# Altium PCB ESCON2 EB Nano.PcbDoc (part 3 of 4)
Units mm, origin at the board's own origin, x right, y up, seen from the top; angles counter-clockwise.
Board outline 67 x 70 mm, 6 copper layers (Top Side, Mid Layer 1, Mid Layer 2, Mid Layer 5, Mid Layer 6, Bottom Side), stack 1.48 mm thick; 293 components, 114 nets, 848 pads, 2005 vias.
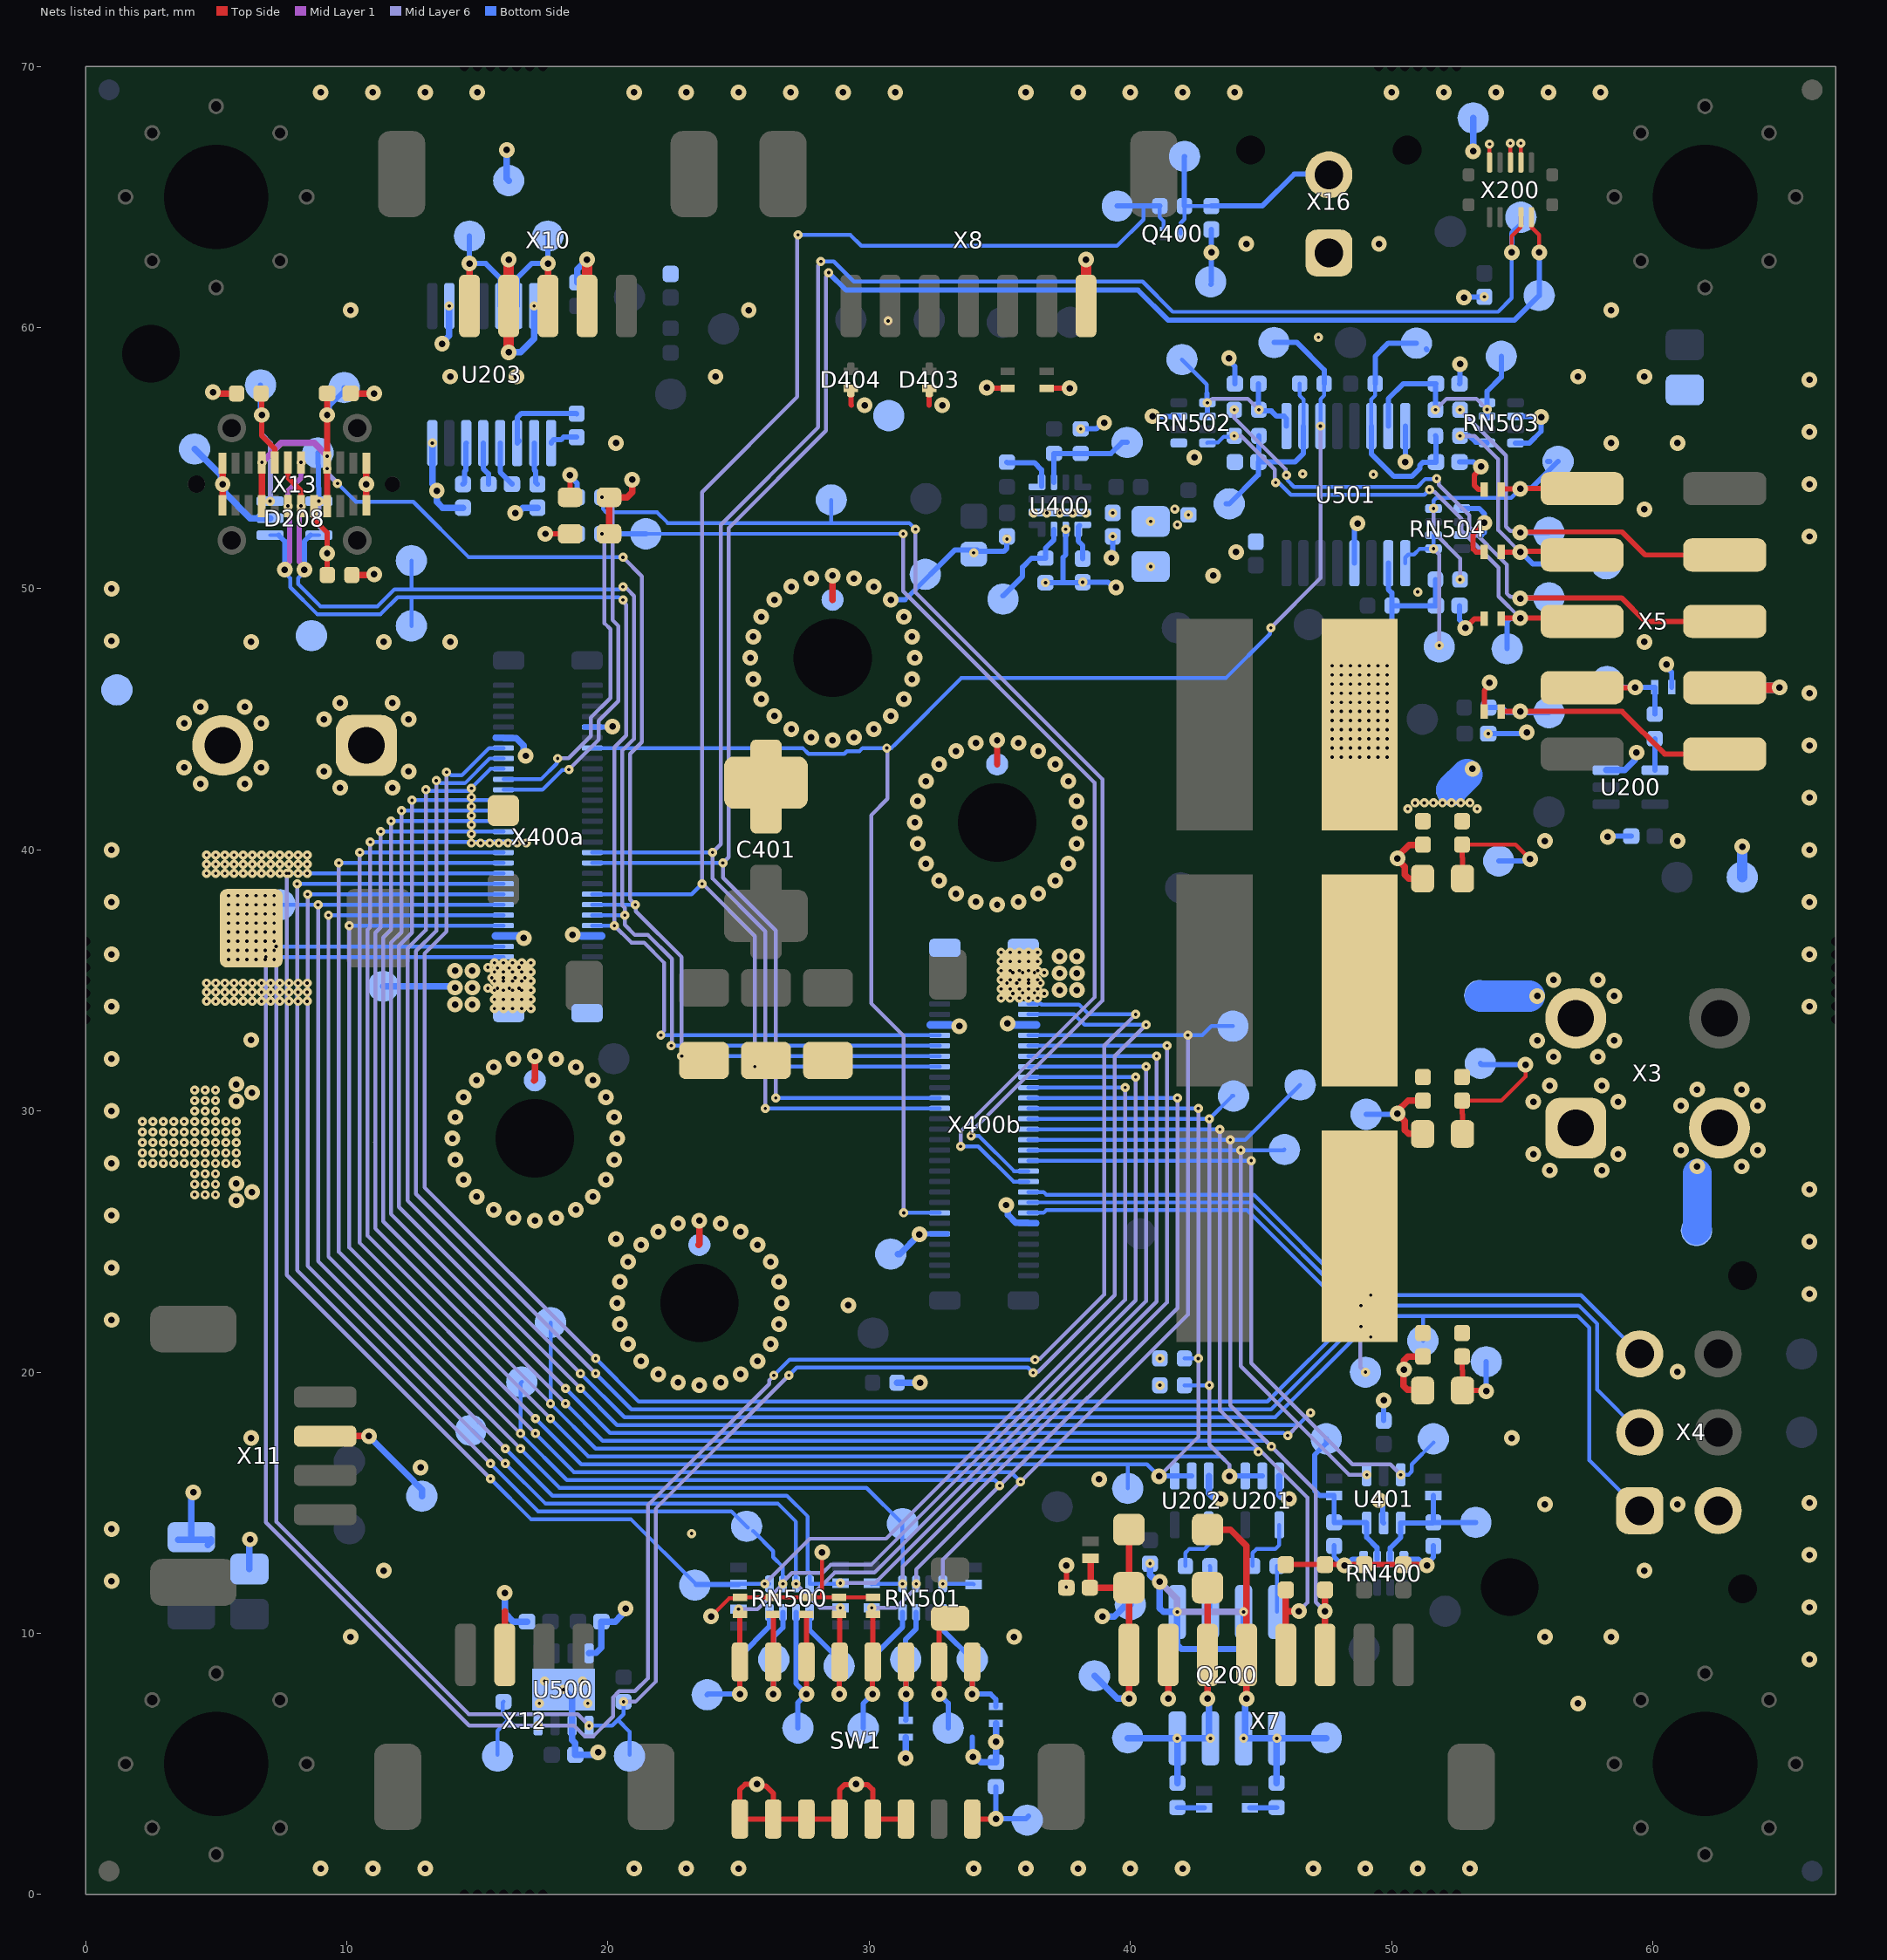
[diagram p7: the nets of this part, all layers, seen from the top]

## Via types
v1: diameter 0.35, hole 0.125, Top Side to Mid Layer 1, tented both sides, 1153 vias
v2: diameter 0.6, hole 0.25, Top Side to Bottom Side, 489 vias
v3: diameter 0.35, hole 0.125, Mid Layer 6 to Bottom Side, tented both sides, 363 vias

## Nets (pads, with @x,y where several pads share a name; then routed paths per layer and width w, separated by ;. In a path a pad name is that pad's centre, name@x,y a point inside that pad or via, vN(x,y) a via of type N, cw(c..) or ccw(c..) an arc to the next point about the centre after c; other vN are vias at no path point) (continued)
C_DigIN3: D210.2 TP269.1 X7.3 X400a.27 X400b.27 | length 90.6
  Top Side w0.25: X7.3@47.45,9.175 v2(47.45,10.85) ; v2(47.45,10.85) D210.2@47.45,11.665
  Mid Layer 6 w0.15: v3(11.7,41.1) 11.7,36.95 11.4,36.65 11.4,25.775 v3(18.375,18.8) ; v3(43.825,28.9) 43.825,18.725 47.1,15.45 47.1,11.2 v2(47.45,10.85)
  Bottom Side w0.15: v3(11.7,41.1) X400a.27@16,41.1 ; v3(18.375,18.8) 19.8,17.375 45.175,17.375 v3(45.4,17.15) ; X400b.27@36.1,28.9 v3(43.825,28.9) 44.4,28.9 TP269.1@46.5,31
C_DigIN4: D209.2 TP270.1 X7.4 X400a.29 X400b.29 | length 90.8
  Top Side w0.25: X7.4@45.95,9.175 45.95,10.9 ; D209.2@45.95,11.665 45.95,10.9 ; v2(46.45,10.85) 46.448,10.852 45.998,10.852 45.95,10.9
  Mid Layer 6 w0.15: v3(11.3,40.7) 11.3,37.025 11.1,36.825 11.1,25.5 v3(17.8,18.8) ; v3(43.425,29.3) 43.425,18.55 46.775,15.2 46.775,11.175 v2(46.45,10.85)
  Bottom Side w0.15: v3(11.3,40.7) X400a.29@16,40.7 ; TP270.1@17.8,21.9 v3(17.8,18.8) 19.525,17.075 44.721,17.075 44.846,16.95 v3(44.9,16.95) v3@44.862,16.912 ; X400b.29@36.1,29.3 v3(43.425,29.3)
C_DigOUT1: D206.2 Q200.5 Q200.6 R202.1 TP224.1 X7.5 | length 14
  Top Side w0.25: D206.2@42.955,13.975 43.825,13.975 44.45,13.35 X7.5@44.45,9.175 v2(44.45,7.5)
  Bottom Side w0.25: v2(44.45,7.5) 44.393,7.443 44.393,6.038 v3(44.335,5.98) Q200.5@45.6,5.98 ; R202.1@45.6,4.27 Q200.5@45.6,5.98 ; TP224.1@47.5,5.98 v3(45.605,5.98) Q200.5@45.6,5.98
C_DigOUT2: D207.2 Q200.7 Q200.8 R203.1 TP225.1 X7.6 | length 10.7
  Top Side w0.25: v2(42.95,7.5) X7.6@42.95,9.175 ; X7.6@42.955,9.175 D207.2@42.955,11.75
  Bottom Side w0.25: TP225.1@39.9,5.98 v3(41.795,5.98) v3(43.065,5.98) 43.008,6.038 43.008,7.443 v2(42.95,7.5) ; R203.1@41.8,4.27 Q200.8@41.8,5.975
C_MotorTemp: C421.2 Q400.3 R427.2 TP260.1 X16.2 | length 9.1
  Bottom Side w0.15: Q400.3@41.925,63.6 41.925,64 42.075,64.15 42.075,64.645 R427.2@42.07,64.65 C421.2@43.1,64.65 ; X16.2@47.575,65.875 X16.2@47.6,65.85
  Bottom Side w0.2: R427.2@42.07,64.65 42.07,66.545 TP260.1@42.075,66.55 ; C421.2@43.1,64.65 45.05,64.65 46.275,65.875 X16.2@47.575,65.875
C_S1_Hall1: TP266.1 X4.1 X400a.13 X400b.13 | length 91.3
  Mid Layer 6 w0.15: v3(13.825,42.975) 13.825,36.875 12.975,36.025 12.975,27.075 v3(19.525,20.525)
  Bottom Side w0.15: v3(13.825,42.975) 13.879,42.975 14.004,42.85 14.4,42.85 15.45,43.9 X400a.13@16,43.9 ; v3(19.525,20.525) 21.175,18.875 45.25,18.875 48.525,22.15 ; X400b.13@36.1,26.1 36.675,26.1 36.775,26.2 44.475,26.2 48.525,22.15 ; TP266.1@51.2,21.2 51.2,22.149 51.199,22.15 ; X4.1@59.5,14.7 57.575,16.625 57.575,21.7 57.125,22.15 51.199,22.15 ; 48.525,22.15 51.199,22.15
C_S1_Hall2: TP267.1 X4.2 X400a.15 X400b.15 | length 91.2
  Mid Layer 6 w0.15: v3(13.425,42.65) 13.425,36.9 12.65,36.125 12.65,26.825 v3(19.525,19.95) ; v3(48.825,22.55) v3(48.825,21.75) 48.8,21.725 48.8,20.201 v3(49.001,20.001)
  Bottom Side w0.15: v3(13.425,42.65) 13.479,42.65 13.579,42.55 14.526,42.55 15.475,43.499 X400a.15@16,43.5 ; v3(19.525,19.95) 20.9,18.575 45.385,18.575 48.56,21.749 v3(48.825,21.75) ; X400b.15@36.1,26.5 44.6,26.5 48.55,22.55 v3(48.825,22.55) 57.175,22.55 57.875,21.85 57.875,19.325 X4.2@59.5,17.7
C_S1_Hall3: TP268.1 X4.3 X400a.17 X400b.17 | length 89.6
  Mid Layer 6 w0.15: v3(13.025,42.3) 13.025,36.925 12.325,36.225 12.325,26.575 v3(18.95,19.95) ; v3(49.2,21.35) 49.225,21.375 49.225,22.925 v3(49.2,22.95)
  Bottom Side w0.15: v3(13.025,42.3) 13.079,42.3 13.129,42.25 14.65,42.25 15.5,43.1 X400a.17@16,43.1 ; v3(18.95,19.95) 20.625,18.275 45.538,18.275 48.613,21.35 v3(49.2,21.35) ; X400b.17@36.1,26.9 36.675,26.9 36.775,26.8 44.725,26.8 48.569,22.956 49.194,22.956 v3(49.2,22.95) ; TP268.1@49.2,24 v3(49.2,22.95) ; X4.3@59.5,20.7 57.25,22.95 v3(49.2,22.95)
C_S2_/A: R503.1 TP216.1 X5.5 | length 24.9
  Top Side w0.2: v2@54.925,49.6 54.975,49.65 58.8,49.65 59.7,48.75 X5.5@62.755,48.75
  Mid Layer 6 w0.15: v3(43.98,56.85) 43.98,56.539 45.939,54.58 45.939,54.386 v3(45.975,54.35) ; v3(51.725,54.22) 51.725,54.166 51.807,54.084 51.807,53.978 52.975,52.81 52.975,52.356 54.406,50.925 54.406,49.819 54.541,49.684 54.866,49.684 v2(54.925,49.625)
  Bottom Side w0.15: v3(45.975,54.35) 46.013,54.312 46.013,54.154 46.268,53.9 50.992,53.9 51.285,54.192 51.697,54.192 v3(51.725,54.22)
  Bottom Side w0.2: v2@54.925,49.6 54.975,49.65 TP216.1@56.025,49.65
C_S2_/B: R505.1 TP218.1 X5.7 | length 15.2
  Top Side w0.2: v2(54.925,52.15) 54.95,52.175 58.825,52.175 59.71,51.29 X5.7@62.755,51.29
  Mid Layer 6 w0.15: v3(52.62,56.85) 54.375,55.095 54.375,52.375 54.541,52.209 54.866,52.209 v2(54.925,52.15)
  Bottom Side w0.2: v2(54.925,52.15) TP218.1@56.025,52.15
C_S2_A_Filt: C503.1 R502.2 R507.2 TP422.1 U501.2 | length 7.8
  Bottom Side w0.15: R507.2@46.48,57.85 46.48,57.395 46.625,57.25 U501.2@46.625,56.225
  Bottom Side w0.2: TP422.1@43.675,53.25 TP422.1@43.785,53.25 44.897,54.362 44.897,54.847 C503.1@44.9,54.85 ; R502.2@44.92,55.85 44.92,54.87 C503.1@44.9,54.85 ; U501.2@46.625,56.225 46.625,55.175 46.3,54.85 C503.1@44.9,54.85
C_S2_A_HsDgin1: D502.2 R502.1 RN502.8 TP217.1 X5.6 | length 21.1
  Top Side w0.2: D502.2@54.2,48.85 54.225,48.875 v2(54.925,48.875) 57.17,48.875 X5.6@57.295,48.75
  Mid Layer 6 w0.15: v3(43.98,55.85) 43.984,55.846 44.242,55.846 45.53,54.558 45.53,54.095 v3(45.56,54.064) ; v3(51.45,53.789) 51.504,53.789 51.583,53.71 51.636,53.71 52.675,52.671 52.675,52.226 54.1,50.801 54.1,49.7 v2(54.925,48.875)
  Bottom Side w0.15: RN502.8@42.945,55.58 42.965,55.6 43.352,55.6 43.575,55.823 43.953,55.823 v3(43.98,55.85) ; v3(45.56,54.064) 45.599,54.026 45.715,54.026 46.144,53.597 51.258,53.597 v3(51.45,53.789)
  Bottom Side w0.2: TP217.1@54.425,47.7 54.425,48.746 54.542,48.863 54.913,48.863 v2(54.925,48.875)
C_S2_B_Filt: C506.1 R504.2 R508.2 TP424.1 U501.6 | length 9.8
  Bottom Side w0.15: U501.6@49.225,56.225 49.225,57.25 49.37,57.395 R508.2@49.37,57.85
  Bottom Side w0.2: U501.6@49.225,56.225 49.225,55.164 50.092,54.296 50.771,54.296 51.075,54.6 51.075,54.719 51.202,54.846 51.696,54.846 C506.1@51.7,54.85 51.7,55.83 R504.2@51.68,55.85 ; R508.2@49.37,57.85 49.37,58.895 49.875,59.4 TP424.1@50.95,59.4 ; TP424.1@51.325,59.175 TP424.1@51.35,59.15
C_S2_B_HsDgin2: D501.2 R504.1 RN503.1 TP219.1 X5.8 | length 13.6
  Top Side w0.2: D501.2@54.2,51.4 v2(54.925,51.4) ; v2@54.925,51.425 57.16,51.425 X5.8@57.295,51.29
  Mid Layer 6 w0.15: v3(52.62,55.85) 53.183,55.85 54.075,54.958 54.075,52.25 v2(54.925,51.4)
  Bottom Side w0.2: v3(52.62,55.85) 52.975,55.85 53.219,55.606 53.629,55.606 RN503.1@53.655,55.58 ; v2@54.863,51.362 54.925,51.425 55.4,50.95 TP219.1@58.225,50.95
C_S2_Clock_HsDgout1: D200.2 R200.2 TP215.1 X5.4 | length 5
  Top Side w0.2: X5.4@57.295,46.21 v2@59.325,46.21
  Bottom Side w0.2: TP215.1@58.25,46.45 58.441,46.259 58.828,46.259 58.867,46.22 v2(59.325,46.22) D200.2@60.075,46.22 ; R200.2@60.075,45.195 D200.2@60.075,46.22 ; D200.2@60.075,46.225 D200.2@60.075,46.22
C_S2_Data_HsDgin4: D503.2 R510.1 TP213.1 X5.1 | length 11.6
  Top Side w0.2: D503.2@54.2,45.3 v2(54.925,45.3) 58.825,45.3 60.455,43.67 X5.1@62.755,43.67
  Bottom Side w0.2: R510.1@53.72,45.45 54.225,45.45 54.4,45.275 54.9,45.275 v2(54.925,45.3) 54.975,45.25 TP213.1@56.025,45.25
C_S2_I_Filt: C508.1 R506.2 R509.2 TP426.1 U501.10 | length 6.2
  Bottom Side w0.2: TP426.1@49.325,47.825 50.02,48.52 R509.2@50.02,49.35 ; U501.10@49.875,50.975 49.875,49.975 50.007,49.843 50.007,49.363 R509.2@50.02,49.35 ; R506.2@51.68,50.35 51.68,49.37 C508.1@51.7,49.35 R509.2@50.02,49.35
C_S2_I_HsDgin3: D500.2 R506.1 RN504.8 TP220.1 X5.10 | length 12
  Top Side w0.2: D500.2@54.2,53.8 54.225,53.825 v2(54.925,53.825) 54.93,53.83 X5.10@57.295,53.83
  Mid Layer 6 w0.15: v3(51.605,53.07) 51.605,52.17 52.62,51.155 v3(52.62,50.35)
  Bottom Side w0.15: v3(51.605,53.07) 51.605,53.38 51.704,53.479 54.579,53.479 v2(54.925,53.825)
  Bottom Side w0.2: v2(54.925,53.825) 54.949,53.849 55.349,53.849 TP220.1@56.375,54.875 ; TP220.1@55.975,54.875 TP220.1@56.05,54.875
C_UART_RxD: TP262.1 U203.13 X10.1 | length 5.2
  Top Side w0.25: X10.1@14.7,60.825 v2@14.7,62.45
  Bottom Side w0.2: TP262.1@14.7,63.5 14.7,62.451 15.325,62.45 15.875,61.9 U203.13@15.875,60.825
  other v2: 14.7,62.45
C_UART_TxD: TP263.1 U203.14 X10.3 | length 5.2
  Top Side w0.25: X10.3@17.7,60.825 v2(17.7,62.45)
  Bottom Side w0.2: U203.14@16.525,60.825 16.525,61.9 17.075,62.45 v2(17.7,62.45) TP263.1@17.7,63.5
C_USB_CC1: D208.3 R207.1 TP249.1 X13.A5 | length 7.5
  Top Side w0.15: R207.1@6.72,57.475 R207.1@6.75,57.445
  Top Side w0.2: R207.1@6.75,57.445 v2(6.75,56.65) 6.75,55.85 7.25,55.35 X13.A5@7.25,54.835
  Mid Layer 6 w0.2: v2(6.75,56.65) 6.75,55.9 7.075,55.575 v3@7.075,53.35
  Bottom Side w0.2: TP249.1@6.7,57.8 6.7,56.771 ccw(c6.871,56.771) v2(6.75,56.65)
  other v3: 7.065,53.35
C_USB_CC2: D208.4 R208.1 TP254.1 X13.B5 | length 6.8
  Top Side w0.15: R208.1@9.25,50.53 R208.1@9.255,50.525
  Top Side w0.2: X13.B5@8.75,53.165 8.75,52.65 9.25,52.15 v2(9.25,51.35) R208.1@9.25,50.53
  Mid Layer 6 w0.15: v3@8.925,53.34 v3(8.935,53.35)
  Mid Layer 6 w0.2: v3@8.925,53.34 8.925,52.425 9.25,52.1 v2(9.25,51.35)
  Bottom Side w0.15: D208.4@8.933,53.444 v3(8.935,53.35)
  Bottom Side w0.2: TP254.1@8.9,55.2 D208.4@8.933,53.444
C_USB_D+: D208.5 TP251.1 X13.A6 X13.B6 X400a.46 X400b.46 | length 51.7
  Top Side w0.2: X13.A6@7.75,54.835 7.75,54.25 8.25,53.75 v1(8.25,53.165)
  Mid Layer 1 w0.2: v1@8.279,53.136 v1(8.25,53.165) 8.25,52.9 8.178,52.828 8.178,51.03 8.375,50.833 v2(8.375,50.725)
  Mid Layer 6 w0.15: v3(20.574,50.075) 20.629,50.075 20.724,49.98 20.745,49.98 21,49.725 21,44.251 20.55,43.801 20.55,37.875 20.65,37.775 v3(20.65,37.5) 20.65,37.124 21.024,36.75 21.525,36.75 22.45,35.825 22.45,32.525 v3(22.425,32.5)
  Bottom Side w0.15: v2(8.375,50.725) 8.375,50.636 8.139,50.4 8.139,50.179 8.993,49.325 11.175,49.325 11.827,49.977 12.475,49.977 ; D208.5@8.608,52.05 D208.5@8.935,52.05 ; TP251.1@12.475,51.075 12.475,49.977 ; X400a.46@19.4,37.5 20.25,37.5 v3(20.65,37.5) ; v3(20.574,50.075) 20.52,50.075 20.422,49.977 12.475,49.977 ; v3(22.425,32.5) X400b.46@32.7,32.5
  Bottom Side w0.2: v2(8.375,50.725) 8.375,51.817 D208.5@8.608,52.05
C_USB_D-: D208.1 TP252.1 X13.A7 X13.B7 X400a.48 X400b.48 | length 51.1
  Mid Layer 1 w0.2: v2(7.625,50.725) 7.625,50.833 7.816,51.024 7.816,52.834 7.753,52.897 7.753,53.162 v1(7.75,53.165) 7.75,53.75 8.25,54.25 v1(8.25,54.835)
  Mid Layer 6 w0.15: v3(20.574,49.571) 20.574,49.517 20.7,49.391 20.7,44.375 20.25,43.925 v3(20.25,37.1) 20.9,36.45 21.378,36.45 22.144,35.683 22.144,33.074 22.025,32.954 v3(22.025,32.9)
  Bottom Side w0.15: D208.1@7.065,52.05 D208.1@7.392,52.05 ; v2(7.625,50.725) 7.625,50.612 7.838,50.399 7.838,50.055 8.868,49.025 11.3,49.025 11.945,49.67 12.5,49.67 ; TP252.1@12.475,48.575 12.475,49.645 12.5,49.67 ; X400a.48@19.4,37.1 v3(20.25,37.1) ; v3@20.52,49.546 v3@20.574,49.546 ; v3(20.574,49.571) 20.52,49.571 20.421,49.67 12.5,49.67 ; v3(22.025,32.9) X400b.48@32.7,32.9
  Bottom Side w0.2: D208.1@7.392,52.05 7.625,51.817 v2(7.625,50.725)
C_USB_VBUS: C206.2 TP247.1 X13.A4 X13.A9 X13.B4 X13.B9 X400a.44 X400b.44 | length 57
  Top Side w0.25: X13.B9@6.75,53.225 v1(6.75,54.835) ; X13.B4@9.25,53.225 v1(9.25,54.6) ; v1(9.25,55.075) v2(9.25,56.65) C206.2@9.25,57.475
  Mid Layer 1 w0.25: v1(6.75,54.835) 7.49,55.575 8.75,55.575 v1(9.25,55.075) v1(9.25,54.6)
  Mid Layer 6 w0.15: v3(20.575,51.2) 21.3,50.475 21.3,44.126 20.85,43.676 20.85,38.1 21.064,37.886 21.064,37.649 22.825,35.888 v3(22.825,32.1)
  Mid Layer 6 w0.2: v2(9.25,56.65) 9.25,54.425 v3(9.65,54.025)
  Bottom Side w0.15: v3(9.65,54.025) 10.35,53.325 12.55,53.325 14.675,51.2 v3(20.575,51.2) ; X400a.44@19.4,37.9 20.65,37.9 v3(21.05,37.9) ; v3(22.825,32.1) X400b.44@32.7,32.1
  Bottom Side w0.2: v2(9.25,56.65) 9.327,56.727 9.327,57.001 9.9,57.574 TP247.1@9.9,57.7
C_VDigIO: C202.2 D201.1 D206.1 D207.1 TP229.1 X7.8 | length 10.8
  Top Side w0.25: D201.1@38.475,12.875 38.475,11.725 38.5,11.75 D207.1@39.945,11.75 ; X7.8@39.945,9.175 D207.1@39.945,11.75 ; D206.1@39.945,13.975 D207.1@39.945,11.75 ; v2(39.95,7.5) X7.8@39.95,9.175
  Bottom Side w0.25: TP229.1@38.625,8.375 39.498,7.502 39.948,7.502 v2(39.95,7.5)
C_VP: F400.1 TP201.1 X1.2
  other v1: 4.635,34.2 4.985,34.2 5.335,34.2 5.685,34.2 6.035,34.2 6.385,34.2 6.735,34.2 7.085,34.2 7.435,34.2 7.785,34.2 8.135,34.2 8.485,34.2 4.635,34.55 4.985,34.55 5.335,34.55 5.685,34.55 6.035,34.55 6.385,34.55 6.735,34.55 7.085,34.55 7.435,34.55 7.785,34.55 8.135,34.55 8.485,34.55 4.635,34.9 4.985,34.9 5.335,34.9 5.685,34.9 6.035,34.9 6.385,34.9 6.735,34.9 7.085,34.9 7.435,34.9 7.785,34.9 8.135,34.9 8.485,34.9 5.475,35.8 5.825,35.8 6.175,35.8 6.525,35.8 6.875,35.8 7.225,35.8 5.475,36.15 5.825,36.15 6.175,36.15 6.525,36.15 6.875,36.15 7.225,36.15 5.475,36.5 5.825,36.5 6.175,36.5 6.525,36.5 6.875,36.5 7.225,36.5 5.475,36.85 5.825,36.85 6.175,36.85 6.525,36.85 6.875,36.85 7.225,36.85 5.475,37.2 5.825,37.2 6.175,37.2 6.525,37.2 6.875,37.2 7.225,37.2 5.475,37.55 5.825,37.55 6.175,37.55 6.525,37.55 6.875,37.55 7.225,37.55 5.475,37.9 5.825,37.9 6.175,37.9 6.525,37.9 6.875,37.9 7.225,37.9 5.475,38.25 5.825,38.25 6.175,38.25 6.525,38.25 6.875,38.25 7.225,38.25 4.635,39.1 4.985,39.1 5.335,39.1 5.685,39.1 6.035,39.1 6.385,39.1 6.735,39.1 7.085,39.1 7.435,39.1 7.785,39.1 8.135,39.1 8.485,39.1 4.635,39.45 4.985,39.45 5.335,39.45 5.685,39.45 6.035,39.45 6.385,39.45 6.735,39.45 7.085,39.45 7.435,39.45 7.785,39.45 8.135,39.45 8.485,39.45 4.635,39.8 4.985,39.8 5.335,39.8 5.685,39.8 6.035,39.8 6.385,39.8 6.735,39.8 7.085,39.8 7.435,39.8 7.785,39.8 8.135,39.8 8.485,39.8
  other v2: 4.4,42.528 6.1,42.528 3.778,43.15 6.722,43.15 3.778,44.85 6.722,44.85 4.4,45.472 6.1,45.472
C_W1: C402.2 C405.2 L400.2 TP207.1 X3.1 | length 0.9
  Bottom Side w0.2: TP207.1@52.3,42.275 TP207.1@52.3,42.3
  Bottom Side w1.2: TP207.1@52.3,42.3 52.888,42.888
  other v1: 50.625,41.575 53.275,41.575 50.9,41.8 51.25,41.8 51.6,41.8 51.95,41.8 52.3,41.8 52.65,41.8 53,41.8 47.725,43.55 48.075,43.55 48.425,43.55 48.775,43.55 49.125,43.55 49.475,43.55 49.825,43.55 47.725,43.9 48.075,43.9 48.425,43.9 48.775,43.9 49.125,43.9 49.475,43.9 49.825,43.9 47.725,44.25 48.075,44.25 48.425,44.25 48.775,44.25 49.125,44.25 49.475,44.25 49.825,44.25 47.725,44.6 48.075,44.6 48.425,44.6 48.775,44.6 49.125,44.6 49.475,44.6 49.825,44.6 47.725,44.95 48.075,44.95 48.425,44.95 48.775,44.95 49.125,44.95 49.475,44.95 49.825,44.95 47.725,45.3 48.075,45.3 48.425,45.3 48.775,45.3 49.125,45.3 49.475,45.3 49.825,45.3 47.725,45.65 48.075,45.65 48.425,45.65 48.775,45.65 49.125,45.65 49.475,45.65 49.825,45.65 47.725,46 48.075,46 48.425,46 48.775,46 49.125,46 49.475,46 49.825,46 47.725,46.35 48.075,46.35 48.425,46.35 48.775,46.35 49.125,46.35 49.475,46.35 49.825,46.35 47.725,46.7 48.075,46.7 48.425,46.7 48.775,46.7 49.125,46.7 49.475,46.7 49.825,46.7 47.725,47.05 48.075,47.05 48.425,47.05 48.775,47.05 49.125,47.05 49.475,47.05 49.825,47.05
  other v2: 56.05,27.728 58.05,27.728 55.428,28.35 58.672,28.35 55.428,30.35 58.672,30.35 56.05,30.972 58.05,30.972 53.1,43.1
C_W2: C403.2 C406.2 L401.2 TP208.1 X3.2 | length 1.9
  Bottom Side w0.2: TP208.1@53.375,34.425 TP208.1@53.4,34.4
  Bottom Side w1.2: TP208.1@53.4,34.4 55.275,34.4
  other v2: 56.2,32.078 57.9,32.078 55.578,32.7 58.522,32.7 55.578,34.4 58.522,34.4 56.2,35.022 57.9,35.022
C_W3: C404.2 C407.2 L402.2 TP209.1 X3.3 | length 2.2
  Bottom Side w1.1: TP209.1@61.675,25.425 61.694,25.444 61.694,25.515 61.7,25.521 v2@61.7,27.625
  other v2: 61.7,27.878 63.4,27.878 61.078,28.5 64.022,28.5 61.078,30.2 64.022,30.2 61.7,30.822 63.4,30.822
CAN_AutoBR: D515.1 RN501.7 SW1.11 TP253.1 | length 5.5
  Top Side w0.2: v2@31.405,7.68 SW1.11@31.405,8.907
  Bottom Side w0.2: D515.1@31.4,6.675 31.41,6.685 v2(31.41,7.675) 31.41,8.99 TP253.1@31.4,9 31.4,9.775 31.8,10.175 RN501.7@31.8,10.805
CAN_AutoBR_n: D513.2 RN501.2 TP414.1 X400a.35 X400b.35 | length 82.8
  Mid Layer 6 w0.15: v3(9.7,39.5) 9.7,24.6 v3(16.65,17.65) ; v3(30.1,10.975) 31.025,10.975 31.762,11.712 31.762,11.857 v3(31.8,11.895) 31.8,12.455 v3(34.996,15.651) 41.8,22.455 v3(41.8,30.5)
  Bottom Side w0.15: v3(9.7,39.5) X400a.35@16,39.5 ; TP414.1@16.7,19.625 16.65,19.575 v3(16.65,17.65) 18.425,15.875 34.808,15.875 34.996,15.687 v3(34.996,15.651) ; X400b.35@36.1,30.5 v3(41.8,30.5)
CAN_ID1: D506.1 RN500.8 SW1.16 TP239.1 | length 7.9
  Top Side w0.2: v2(25.05,7.675) 25.05,8.902 SW1.16@25.055,8.907 25.055,10.72 D506.1@25.05,10.725
  Bottom Side w0.2: TP239.1@23.8,7.65 23.825,7.675 v2(25.05,7.675) 25.05,9.125 26.18,10.255 RN500.8@26.18,10.805
CAN_ID1_n: D504.2 RN500.1 TP405.1 X400a.37 X400b.37 | length 77.2
  Mid Layer 6 w0.15: v3(7.7,39.1) 7.7,23.725 v3(15.5,15.925) ; v3(26,11.9) 27.725,13.625 30.65,13.625 39.8,22.775 v3(39.8,30.9)
  Bottom Side w0.15: v3(7.7,39.1) X400a.37@16,39.1 ; v3(15.5,15.925) 17.05,14.375 20.875,14.375 TP405.1@23.375,11.875 ; D504.2@25,11.875 25.02,11.895 RN500.1@26.18,11.895 ; X400b.37@36.1,30.9 v3(39.8,30.9)
  Bottom Side w0.2: TP405.1@23.375,11.875 D504.2@25,11.875
CAN_ID2: D510.1 RN500.7 SW1.15 TP243.1 | length 6.3
  Top Side w0.2: D510.1@26.3,10.725 26.325,10.7 SW1.15@26.325,8.907 26.325,7.68 v2(26.33,7.675)
  Bottom Side w0.2: v2(26.33,7.675) 26.33,8.98 TP243.1@26.35,9 26.35,9.875 26.7,10.225 RN500.7@26.7,10.805
CAN_ID2_n: D508.2 RN500.2 TP408.1 X400a.39 X400b.39 | length 79.3
  Mid Layer 6 w0.15: v3(8.1,38.7) 8.1,23.9 v3(15.5,16.5) ; v3(25,10.925) 25.73,10.925 v3(26.7,11.895) 26.7,11.949 26.795,12.044 26.795,12.065 27.043,12.313 28.213,12.313 28.525,12.625 30.075,12.625 40.2,22.75 v3(40.2,31.3)
  Bottom Side w0.15: v3(8.1,38.7) X400a.39@16,38.7 ; v3(15.5,16.5) 17.325,14.675 24.725,14.675 TP408.1@25.35,14.05 ; TP408.1@25.562,13.912 26.325,13.15 26.325,12.912 26.7,12.537 v3(26.7,11.895) RN500.2@26.725,11.92 ; X400b.39@36.1,31.3 v3(40.2,31.3)
CAN_ID3: D514.1 RN500.6 SW1.14 TP245.1 | length 7.8
  Top Side w0.2: v2@27.595,7.68 SW1.14@27.595,8.907 27.595,10.72 D514.1@27.6,10.725
  Bottom Side w0.2: RN500.6@27.2,10.805 27.2,8.075 v2(27.6,7.675) 27.275,7.35 TP245.1@27.275,6.375
CAN_ID3_n: D512.2 RN500.3 TP413.1 X400a.41 X400b.41 | length 81.9
  Mid Layer 6 w0.15: v3(8.5,38.3) 8.5,24.075 v3(16.075,16.5) ; v3(27.2,11.895) 27.685,11.41 ; v3(28.9,10.975) 28.12,10.975 27.685,11.41 ; v3(40.6,31.7) 40.6,22.725 30.2,12.325 28.675,12.325 27.76,11.41 27.685,11.41
  Bottom Side w0.15: v3(8.5,38.3) X400a.41@16,38.3 ; TP413.1@14.8,17.775 v3(16.075,16.5) 17.6,14.975 26.5,14.975 27.2,14.275 v3(27.2,11.895) ; TP413.1@15.05,18.075 TP413.1@15.1,18.075 ; X400b.41@36.1,31.7 v3(40.6,31.7)
CAN_ID4: D517.1 RN500.5 SW1.13 TP248.1 | length 6.7
  Top Side w0.2: D517.1@28.85,10.725 28.865,10.71 SW1.13@28.865,8.907 28.86,8.902 v2(28.86,7.675)
  Bottom Side w0.2: RN500.5@27.72,10.805 27.72,10.13 28.85,9 28.86,8.99 v2(28.86,7.675)
CAN_ID4_n: D516.2 RN500.4 TP415.1 X400a.43 X400b.43 | length 79.7
  Mid Layer 6 w0.15: v3(8.9,37.9) 8.9,24.25 v3(16.075,17.075) ; v3(28.9,11.925) 30.225,11.925 41,22.7 v3(41,32.1)
  Bottom Side w0.15: TP415.1@7.45,37.9 v3(8.9,37.9) X400a.43@16,37.9 ; v3(16.075,17.075) 17.875,15.275 26.85,15.275 27.65,14.475 27.65,12.4 27.725,12.325 27.725,11.9 RN500.4@27.72,11.895 28.88,11.895 D516.2@28.9,11.875 ; X400b.43@36.1,32.1 v3(41,32.1)
CAN_ID5: D507.1 RN501.8 SW1.12 TP250.1 | length 8.1
  Top Side w0.2: v2(30.13,7.675) 30.13,8.902 SW1.12@30.135,8.907 30.135,10.71 D507.1@30.15,10.725
  Bottom Side w0.2: TP250.1@29.775,6.375 29.775,7.32 v2(30.13,7.675) 30.13,9.095 31.28,10.245 RN501.8@31.28,10.805
CAN_ID5_n: D505.2 RN501.1 TP406.1 X400a.45 X400b.45 | length 79.6
  Mid Layer 6 w0.15: v3(9.3,37.5) 9.3,24.425 v3(16.65,17.075) ; v3(31.28,11.895) 31.28,12.555 41.4,22.675 v3(41.4,32.5)
  Bottom Side w0.15: v3(9.3,37.5) X400a.45@16,37.5 ; v3(16.65,17.075) 18.15,15.575 29.9,15.575 TP406.1@31.275,14.2 31.275,13.4 31.28,13.395 v3(31.28,11.895) 30.12,11.895 D505.2@30.1,11.875 ; X400b.45@36.1,32.5 v3(41.4,32.5)
CAN_ID6: D511.1 RN501.5 SW1.9 TP257.1 | length 6.1
  Top Side w0.2: v2(33.94,7.675) 33.94,8.902 SW1.9@33.945,8.907
  Bottom Side w0.2: RN501.5@32.82,10.805 32.82,10.13 TP257.1@33.95,9 33.95,7.685 v2(33.94,7.675) 34.65,7.675 34.85,7.475 D511.1@34.85,7.2
CAN_ID6_n: D509.2 RN501.4 TP411.1 X400a.47 X400b.47 | length 81.7
  Mid Layer 6 w0.15: v3(10.1,37.1) 10.1,24.775 v3(17.225,17.65) ; v3(32.82,11.895) 32.82,12.825 42.2,22.205 v3(42.2,32.9)
  Bottom Side w0.15: v3(10.1,37.1) X400a.47@16,37.1 ; v3(17.225,17.65) 18.7,16.175 35.425,16.175 v3(35.8,15.8) ; v3(32.82,11.895) 33.98,11.895 D509.2@34,11.875 ; X400b.47@36.1,32.9 v3(42.2,32.9) 42.75,32.9 43.1,33.25 TP411.1@43.925,33.25
CAN_RX: R500.1 TP412.1 U500.4 X400a.53 X400b.53 | length 96.7
  Mid Layer 6 w0.15: v3(6.9,35.9) 6.9,14.25 14.685,6.465 v3(17.325,6.465) 18.701,6.465 19.107,6.06 19.438,6.06 20.197,6.818 20.197,7.546 20.435,7.784 21.034,7.784 21.525,8.274 21.525,14.9 26.175,19.55 26.175,19.687 26.35,19.862 v3(26.35,19.875) ; v3(36.35,20.475) 36.388,20.513 36.538,20.513 39,22.975 39,32.5 v3(40.2,33.7)
  Bottom Side w0.15: v3(6.9,35.9) X400a.53@16,35.9 ; TP412.1@15.775,5.35 15.775,6.265 16.192,6.683 ; R500.1@16,7.38 15.975,7.355 15.975,6.9 16.192,6.683 ; v3(17.325,6.465) 16.41,6.465 16.192,6.683 ; v3(26.35,19.875) 26.951,20.476 36.349,20.476 v3(36.35,20.475) ; X400b.53@36.1,34.1 36.575,34.1 36.6,34.075 38.038,34.075 38.412,33.7 v3(40.2,33.7)
CAN_TX: R501.1 TP407.1 U500.1 X400a.51 X400b.51 | length 94.2
  Mid Layer 6 w0.15: v3(7.3,36.3) 7.3,14.274 14.674,6.9 18.84,6.9 v3(19.275,6.465) ; v3(20.6,7.38) 21.055,7.38 21.825,8.15 21.825,14.775 v3(26.925,19.875) ; v3(36.278,19.978) 36.308,20.008 36.458,20.008 39.4,22.95 39.4,32.1 v3(40.6,33.3)
  Bottom Side w0.15: v3(7.3,36.3) X400a.51@16,36.3 ; v3(19.275,6.465) 20.165,6.465 20.383,6.683 ; v3(20.6,7.38) 20.6,6.9 20.383,6.683 ; TP407.1@20.825,5.35 20.825,6.24 20.383,6.683 ; v3(26.925,19.875) 27.225,20.175 36.081,20.175 v3(36.278,19.978) ; X400b.51@36.1,33.7 37.85,33.7 38.25,33.3 v3(40.6,33.3)
DBG_SWCLK: TP222.1 X200.4 X400a.34 X400b.34 | length 78.5
  Top Side w0.15: v2(54.6,62.875) 54.6,63.495 54.95,63.845 X200.4@54.95,64.23
  Mid Layer 6 w0.15: v3(26.025,30.1) 26.025,36.882 24,38.907 v3(24,39.9) 24.319,40.219 24.319,52.444 28.05,56.175 28.05,62.371 28.15,62.471 v3(28.15,62.525)
  Bottom Side w0.15: X400a.34@19.4,39.9 v3(24,39.9) ; v3@26.025,30.1 X400b.34@32.7,30.1 ; v3(28.15,62.525) 28.65,62.525 29.415,61.76 40.465,61.76 41.625,60.6 54.075,60.6 54.6,61.125 v2(54.6,62.875)
  Bottom Side w0.2: v2(54.6,62.875) 54.6,63.608 54.95,63.958 TP222.1@54.95,64.225
DBG_SWDIO: TP221.1 X200.2 X400a.36 X400b.36 | length 76.9
  Top Side w0.15: X200.2@55.35,64.23 55.35,63.845 55.65,63.545 v2(55.65,62.875)
  Mid Layer 6 w0.15: v3(26.425,30.5) 26.425,36.909 24.4,38.934 v3(24.4,39.5) 24.619,39.719 24.619,52.319 28.35,56.05 28.35,61.946 28.45,62.046 v3(28.45,62.1)
  Bottom Side w0.15: X400a.36@19.4,39.5 v3(24.4,39.5) ; v3(26.425,30.5) X400b.36@32.7,30.5
  Bottom Side w0.2: v3(28.45,62.1) 29.115,61.435 40.29,61.435 41.45,60.275 54.7,60.275 TP221.1@55.65,61.225 v2(55.65,62.875)
DigIN1: TP430.1 U401.6 X400a.23 X400b.23 | length 83.9
  Mid Layer 6 w0.15: v3(12.5,41.9) 12.5,36.825 12,36.325 12,26.325 v3(18.95,19.375) ; v3(44.625,28.1) 44.625,20.35 46.7,18.275 ; v3@46.858,18.408 v3@46.862,18.404 ; v3@46.862,18.412 v3(46.9,18.45) 46.887,18.45 46.712,18.275 46.7,18.275 ; v3(50.35,16.075) 49.95,16.475 48.5,16.475 46.7,18.275
  Bottom Side w0.15: v3(12.5,41.9) X400a.23@16,41.9 ; v3(18.95,19.375) 20.35,17.975 46.425,17.975 v3(46.9,18.45) ; X400b.23@36.1,28.1 v3(44.625,28.1) ; v3(50.35,16.075) 50.352,16.077 50.652,16.077 50.775,16.2 50.775,16.475 TP430.1@51.6,17.3
DigIN2: TP431.1 U401.4 X400a.25 X400b.25 | length 82.6
  Mid Layer 6 w0.15: v3(12.1,41.5) 12.1,36.85 11.7,36.45 11.7,26.05 v3(18.375,19.375) ; v3(44.225,28.5) 44.225,20.225 46.45,18 ; v3(46.025,17.575) 46.45,18 ; v3(49.05,16.075) 48.375,16.075 46.45,18
  Bottom Side w0.15: v3(12.1,41.5) X400a.25@16,41.5 ; v3(18.375,19.375) 20.075,17.675 45.871,17.675 45.971,17.575 v3(46.025,17.575) ; X400b.25@36.1,28.5 v3(44.225,28.5) 45.875,28.5 TP431.1@45.9,28.525
DigOUT1: R214.2 TP235.1 U201.1 U201.2 X400a.31 X400b.31 | length 81.7
  Mid Layer 6 w0.15: v3(10.9,40.3) 10.9,37.05 10.8,36.95 10.8,25.225 v3(17.8,18.225) ; v3(43.025,29.7) v3(43.025,19.5) 43.025,17.225 43.8,16.45 v2(43.8,16.015)
  Bottom Side w0.15: v3(10.9,40.3) X400a.31@16,40.3 ; v3(17.8,18.225) 19.25,16.775 43.475,16.775 43.8,16.45 v2(43.8,16.015) ; X400b.31@36.1,29.7 v3(43.025,29.7) 43.9,30.575 TP235.1@43.95,30.575 ; R214.2@42.07,19.5 v3(43.025,19.5)
  Bottom Side w0.2: v2(43.8,16.015) 43.81,16.025 U201.2@45.05,16.025
DigOUT2: R215.2 TP236.1 U202.1 U202.2 X400a.33 X400b.33 | length 78.7
  Mid Layer 6 w0.15: v3(10.5,39.9) 10.5,24.95 v3(17.225,18.225) ; v2(41.1,16.015) 42.6,17.515 v3(42.6,20.525) v3(42.6,30.1)
  Bottom Side w0.15: v3(10.5,39.9) X400a.33@16,39.9 ; v3(17.225,18.225) 18.975,16.475 39.9,16.475 ; X400b.33@36.1,30.1 v3(42.6,30.1) ; TP236.1@39.9,15.55 39.9,16.475 ; v2(41.1,16.015) 40.64,16.475 39.9,16.475 ; R215.2@42.07,20.525 v3(42.6,20.525)
  Bottom Side w0.2: v2(41.1,16.015) 41.11,16.025 U202.2@42.35,16.025
GND: C200.1 C201.1 C202.1 C203.1 C204.1 C205.1 C206.1 C207.2 C208.1 C209.2 C212.1 C400.2 C401.2 C405.1 C406.1 C407.1 C408.1 C409.1 C410.1 C411.1 C412.1 C413.1 C414.1 C415.1 C416.1 C417.1 C418.2 C419.2 C420.1 C421.1 C500.2 C501.2 C502.1 C503.2 C504.2 C505.2 C506.2 C507.2 C508.2 C509.2 D200.1 D202.1 D203.1 D208.2 D209.1 D210.1 D400.2 D403.2 D404.2 D405.1 D406.1 D500.1 D501.1 D502.1 D503.1 D506.2 D507.2 D510.2 D511.2 D514.2 D515.2 D517.2 DS200.1 DS201.1 MP400.1 MP401.1 MP402.1 MP403.1 Q200.1 Q200.3 R206.1 R207.2 R208.2 R210.1 R213.1 R214.1 R215.1 R406.1 R407.1 R408.1 R424.1 R425.1 R428.1 RN400.1 RN400.4 RN502.1 RN502.3 RN503.6 RN503.8 RN504.1 RN504.3 SW1.1 SW1.2 SW1.3 SW1.4 SW1.5 SW1.6 TP200.1 TP203.1 TP214.1 TP226.1 TP227.1 TP238.1 TP242.1 TP246.1 TP259.1 TP264.1 TP265.1 TP403.1 TP409.1 TP433.1 U200.3 U201.3 U202.3 U203.8 U203.10 U203.15 U400.8 U401.2 U500.2 U500.8 U500.9 U501.8 U501.12 X1.1 X4.4 X5.3 X7.7 X8.7 X10.2 X10.4 X11.3 X12.3 X13.A1 X13.A12 X13.B1 X13.B12 X16.1 X200.3 X200.5 X200.9 X400a.0b X400a.10 X400a.11 X400a.49 X400a.50 X400a.55 X400a.57 X400a.59 X400b.0b X400b.10 X400b.11 X400b.49 X400b.50 X400b.55 X400b.57 X400b.59 | length 180.6
  Top Side w0.15: v2(23.95,10.65) 24.646,11.346 25.021,11.346 D506.2@25.05,11.375 D510.2@26.3,11.375 D514.2@27.6,11.375 28.225,11.375 ; v2(28.2,13.1) 28.2,11.4 28.225,11.375 ; D507.2@30.15,11.375 D517.2@28.85,11.375 28.225,11.375 ; X200.9@53.75,66.32 v1(53.75,67.025) ; X200.5@54.55,66.32 v1(54.55,67.05) ; X200.3@54.95,66.32 v1(54.95,67.05)
  Top Side w0.2: D404.2@29.3,57.675 29.3,57.05 29.325,57.025 ; SW1.6@31.405,2.893 SW1.5@30.135,2.893 30.135,4.015 29.937,4.213 29.512,4.213 v2(29.5,4.225) 29.488,4.213 29.063,4.213 28.875,4.025 28.875,2.903 SW1.4@28.865,2.893 SW1.3@27.595,2.893 SW1.2@26.325,2.893 ; 32.3,57.025 D403.2@32.3,57.675 ; v2(34.5,57.7) 34.525,57.675 D406.1@35.3,57.675 ; D405.1@36.8,57.675 v2(37.675,57.675) ; v1(37.55,11.775) v2(37.55,12.6) ; D209.1@45.95,12.635 D210.1@47.45,12.635 51.315,12.635 v2(51.35,12.6) ; v2(52.825,48.5) 53.175,48.85 D502.1@53.55,48.85 ; v2(53.425,54.675) 53.425,54.608 53.175,54.358 53.175,53.95 53.325,53.8 D500.1@53.55,53.8 ; D503.1@53.55,45.3 53.55,46.092 53.75,46.292 v2(53.75,46.4) ; D501.1@53.55,51.4 53.242,51.4 53.125,51.517 53.125,52.1 v2(53.55,52.525) ; SW1.2@26.325,2.893 26.325,3.875 26.052,4.148 25.777,4.148 v2(25.7,4.225) 25.25,4.225 25.055,4.03 SW1.1@25.055,2.893 SW1.2@26.325,2.893
  Top Side w0.25: v2(4.875,57.525) 4.925,57.475 R207.2@5.78,57.475 ; X13.B12@5.25,53.195 v2(5.25,54) X13.A1@5.25,54.805 ; X11.3@9.175,17.55 v2@10.85,17.55 ; C206.1@10.15,57.475 v2(11.05,57.475) ; R208.2@10.195,50.525 11.025,50.525 v2(11.05,50.55) ; X13.B1@10.75,53.195 X13.A12@10.75,54.805 ; X12.3@16.05,9.175 16.05,10.85 ; 17.175,31.175 17.2,31.2 v2(17.2,32.1) ; DS200.1@20.045,52.1 DS201.1@20.045,53.5 20.725,53.5 20.925,53.7 v2(20.925,54.175) ; 23.475,24.875 23.5,24.9 v2(23.5,25.8) ; 28.6,49.575 v2(28.6,50.5) ; 34.9,43.275 v2(34.9,44.2) ; v2(41.45,7.5) X7.7@41.45,9.175 ; R407.1@50.872,29.471 51.185,29.158 R407.1@51.185,29.125 50.652,29.125 50.506,29.271 50.506,29.619 v2(50.225,29.9) 50.225,29.995 50.63,30.4 C406.1@51.2,30.4 ; R406.1@50.872,39.227 51.185,38.914 R406.1@51.185,38.9 50.652,38.9 50.506,39.046 50.506,39.355 50.225,39.636 v2(50.225,39.675) 50.225,39.743 50.666,40.185 51.185,40.185 C405.1@51.2,40.2 ; R408.1@51.185,19.3 51.16,19.325 50.6,19.325 50.45,19.475 50.45,20.075 v2(50.475,20.1) 50.475,20.454 50.621,20.6 C407.1@51.2,20.6
  Top Side w0.4: v2(16.2,59.05) X10.2@16.2,60.825 v2(16.2,62.6) ; X10.4@19.2,60.825 v2(19.2,62.6) ; X8.7@38.3,60.825 v2(38.3,62.6) ; X5.3@62.755,46.21 v2@64.85,46.21
  Mid Layer 6 w0.25: v2(41.125,11.975) 41.795,11.305 v3(41.795,10.82) v3(44.335,10.82)
  Bottom Side w0.2: v2(5.25,54) v2@5.327,53.923 ; X400a.10@19.1,44.7 X400a.10@19.4,44.7 v2@20.175,44.7 ; v2(30.827,49.577) 31.377,49.577 33.275,51.475 C413.1@34.125,51.475 ; v2@31.925,25.3 X400b.10@33,25.3 ; 33.95,6.025 33.95,5.3 v2(33.975,5.275) ; v3(34,51.375) C413.1@34.05,51.325 ; C413.1@34.175,51.425 35.158,51.425 35.275,51.542 C414.1@35.275,52 ; v3(36.75,50.23) 37.453,50.23 ; v3(37.525,52.275) 37.525,51.3 37.425,51.2 37.425,50.258 37.453,50.23 ; v3(38.1,56.12) 38.698,56.12 38.928,56.35 v2(39,56.35) ; v2@39.325,51.225 v3(39.325,52) ; v2(39.45,50.05) 39.342,50.05 39.142,50.25 v3(38.175,50.25) 38.155,50.23 37.453,50.23 ; v2(40.85,56.6) RN502.3@41.855,56.6 ; TP259.1@43.075,61.65 TP259.1@43.1,61.675 ; TP259.1@43.1,61.775 C421.1@43.1,63.75 ; v2(43.775,58.825) 43.775,58.733 44,58.508 C505.2@44,57.85 ; C419.2@47.8,13.35 47.8,12.925 48.125,12.6 v2(48.2,12.6) 48.257,12.6 48.502,12.845 RN400.1@48.93,12.845 ; U501.12@48.575,50.975 48.575,52.267 48.7,52.392 v2(48.7,52.5) ; TP433.1@49.025,29.875 50.2,29.875 v2(50.225,29.9) ; v2(49.525,15.1) 49.525,14.992 49.662,14.855 49.662,14.263 U401.2@49.7,14.225 ; C420.1@49.7,18.15 v2(49.7,18.925) ; RN400.4@50.47,12.845 51.033,12.845 51.278,12.6 v2(51.35,12.6) 51.35,12.667 51.6,12.917 C418.2@51.6,13.35 ; v2(50.525,54.85) U501.8@50.525,56.225 ; C508.2@52.6,49.35 52.6,48.802 52.825,48.577 v2(52.825,48.5) ; C506.2@52.6,54.85 53.142,54.85 53.317,54.675 v2(53.425,54.675) ; C507.2@52.6,57.85 52.613,57.862 52.613,58.588 v2(52.625,58.6) ; RN504.3@52.695,52.05 53.45,52.05 53.55,52.15 v2(53.55,52.525) 53.55,52.875 53.355,53.07 RN504.1@52.695,53.07 ; v2(52.775,61.15) 52.788,61.163 53.538,61.163 v3(53.55,61.175) ; v3(53.7,44.45) 55.125,44.45 v2(55.175,44.5) ; RN503.8@54.745,55.58 55.28,55.58 55.725,56.025 v2(55.725,56.575) 55.7,56.6 RN503.6@54.745,56.6 ; v2@58.3,40.525 C200.1@59.175,40.525 ; v2(60.525,47.1) 60.525,46.998 60.725,46.798 D200.1@60.725,46.225
  Bottom Side w0.25: R206.1@3.55,13.58 4.78,13.58 4.8,13.6 4.8,13.505 R206.1@4.675,13.38 ; R206.1@4.05,13.58 4.05,15.23 4.125,15.305 v2(4.125,15.4) ; TP246.1@4.175,55.35 5.183,54.342 5.183,54.067 v2(5.25,54) ; v2@5.327,53.923 5.327,53.673 6.3,52.7 D208.2@7.065,52.7 ; C204.1@6.275,12.465 6.275,13.575 v2(6.3,13.6) ; v2(10.85,17.55) 12.573,15.827 12.573,15.809 12.875,15.507 TP242.1@12.875,15.25 ; TP409.1@11.4,34.775 14.1,34.775 v2(14.15,34.725) ; v3(13.275,55.575) 13.275,54.019 13.45,53.845 v2(13.45,53.75) 13.45,53.325 13.675,53.1 C209.2@14.45,53.1 ; v2(13.65,59.375) 13.65,59.408 13.925,59.683 v3(13.925,60.825) ; X400a.11@15.7,44.3 X400a.11@16,44.3 16.025,44.275 16.487,44.275 16.766,43.996 16.766,43.659 v2@16.825,43.6 ; v2(16.05,11.55) 16.05,10.775 16.375,10.45 C500.2@16.9,10.45 ; v2(16.125,66.8) 16.125,65.7 TP264.1@16.2,65.625 ; v2(16.2,59.05) 16.203,59.053 16.653,59.053 17.175,59.575 v3(17.175,60.825) ; v2(16.45,52.9) 16.545,52.9 16.745,53.1 C208.1@17.3,53.1 ; v3(18.3,7.85) 18.625,7.525 U500.2@18.625,6.465 18.625,5.925 18.75,5.8 C502.1@18.75,5.35 19.43,5.35 19.53,5.45 v2(19.625,5.45) ; C207.2@18.825,61.725 18.825,62.225 v2(19.2,62.6) ; U500.8@19.275,9.235 19.29,9.25 19.55,9.25 19.75,9.45 C501.2@19.75,10.45 20.275,10.45 20.5,10.675 20.5,10.68 20.675,10.855 v2(20.675,10.95) ; R428.1@31.07,19.6 v2(31.95,19.6) ; TP403.1@31.1,24.525 31.175,24.525 v2(31.925,25.275) ; v2(31.4,5.225) D515.2@31.4,6.025 ; v2(33.975,5.275) 34.07,5.275 34.275,5.07 R210.1@34.85,5.07 v2(34.85,5.85) D511.2@34.85,6.55 ; v2(35.25,26.4) 35.317,26.333 35.317,26.021 35.613,25.725 36.075,25.725 X400b.11@36.1,25.7 X400b.11@36.4,25.7 ; v2@38.206,62.6 v2(38.3,62.6) ; v2(38.925,10.65) v2(38.925,10.65) 39.379,10.651 39.828,11.1 TP226.1@40,11.1 ; v3(40.75,12.675) 40.75,12.225 40.835,12.14 40.865,12.14 41.03,11.975 v2(41.125,11.975) 41.125,10.966 41.271,10.82 v3(41.795,10.82) 41.795,9.555 41.95,9.4 44.189,9.4 44.335,9.546 v3(44.335,10.82) ; U202.3@43,16.025 43,15.375 43.158,15.217 43.383,15.217 v2(43.45,15.15) ; U201.3@45.7,16.025 45.7,15.296 45.779,15.217 46.008,15.217 v2(46.075,15.15) ; v2(53.125,66.75) TP265.1@53.125,68.025 ; U200.3@58.215,43.05 58.925,43.05 59.308,43.433 59.308,43.658 v2(59.375,43.725)
  Bottom Side w0.3: X400a.49@15.7,36.7 X400a.49@16,36.7 v2@16.775,36.7 ; v2@18.651,36.754 19,36.7 X400a.50@19.4,36.7 X400a.50@19.75,36.7 ; X400b.50@32.35,33.3 33.1,33.3 v2@33.449,33.246 ; v2@35.325,33.3 X400b.49@36.1,33.3 X400b.49@36.4,33.3
  Bottom Side w0.4: v2(58.275,40.5) v2@58.3,40.525 ; TP203.1@63.425,38.95 v2(63.425,40.125) ; TP214.1@63.7,46.2 64.84,46.2 v2(64.855,46.215)
  other v1: 4.175,26.8 4.575,26.8 4.975,26.8 4.175,27.2 4.575,27.2 4.975,27.2 4.175,27.6 4.575,27.6 4.975,27.6 2.175,28 2.575,28 2.975,28 3.375,28 3.775,28 4.175,28 4.575,28 4.975,28 5.375,28 5.775,28 2.175,28.4 2.575,28.4 2.975,28.4 3.375,28.4 3.775,28.4 4.175,28.4 4.575,28.4 4.975,28.4 5.375,28.4 5.775,28.4 2.175,28.8 2.575,28.8 2.975,28.8 3.375,28.8 3.775,28.8 4.175,28.8 4.575,28.8 4.975,28.8 5.375,28.8 5.775,28.8 2.175,29.2 2.575,29.2 2.975,29.2 3.375,29.2 3.775,29.2 4.175,29.2 4.575,29.2 4.975,29.2 5.375,29.2 5.775,29.2 2.175,29.6 2.575,29.6 2.975,29.6 3.375,29.6 3.775,29.6 4.175,29.6 4.575,29.6 4.975,29.6 5.375,29.6 5.775,29.6 4.175,30 4.575,30 4.975,30 4.175,30.4 4.575,30.4 4.975,30.4 4.175,30.8 4.575,30.8 4.975,30.8 15.65,33.925 16,33.925 16.35,33.925 16.7,33.925 17.05,33.925 15.65,34.275 16,34.275 16.35,34.275 16.7,34.275 17.05,34.275 35.05,34.325 35.4,34.325 35.75,34.325 36.1,34.325 36.45,34.325 15.65,34.625 16,34.625 16.35,34.625 16.7,34.625 17.05,34.625 35.05,34.675 35.4,34.675 35.75,34.675 36.1,34.675 36.45,34.675 15.65,34.975 16,34.975 16.35,34.975 16.7,34.975 17.05,34.975 35.05,35.025 35.4,35.025 35.75,35.025 36.1,35.025 36.45,35.025 15.65,35.325 16,35.325 16.35,35.325 16.7,35.325 17.05,35.325 35.05,35.375 35.4,35.375 35.75,35.375 36.1,35.375 36.45,35.375 15.65,35.675 16,35.675 16.35,35.675 16.7,35.675 17.05,35.675 35.05,35.725 35.4,35.725 35.75,35.725 36.1,35.725 36.45,35.725 35.05,36.075 35.4,36.075 35.75,36.075 36.1,36.075 36.45,36.075 14.775,40.26 15.125,40.26 15.475,40.26 15.825,40.26 16.175,40.26 16.525,40.26 16.875,40.26 14.775,40.61 14.775,40.96 14.775,41.31 14.775,41.66 14.775,42.01 14.775,42.36
  other v2: 9,1 11,1 13,1 21,1 23,1 25,1 34,1 36,1 38,1 40,1 42,1 47,1 49,1 51,1 53,1 57.14,7.32 66,9 10.15,9.86 35.55,9.86 55.87,9.86 58.41,9.86 66,11 1,12 11.42,12.4 59.68,12.4 66,13 1,14 55.87,14.94 60.95,14.94 66,15 38.8,15.9 12.825,16.35 6.34,17.48 54.6,17.48 23.5,19.5 22.685,19.607 24.315,19.607 21.925,19.922 25.075,19.922 60.95,20.02 21.273,20.423 25.727,20.423 20.772,21.075 26.228,21.075 20.457,21.835 26.543,21.835 1,22 29.2,22.56 20.35,22.65 26.65,22.65 66,23 20.457,23.465 26.543,23.465 1,24 20.772,24.225 26.228,24.225 21.273,24.877 25.727,24.877 66,25 20.31,25.1 21.925,25.378 25.075,25.378 22.685,25.693 24.315,25.693 17.2,25.8 16.385,25.907 18.015,25.907 1,26 15.625,26.222 18.775,26.222 5.775,26.575 14.973,26.723 19.427,26.723 6.375,26.9 66,27 5.775,27.225 14.472,27.375 19.928,27.375 1,28 14.157,28.135 20.243,28.135 14.05,28.95 20.35,28.95 14.157,29.765 20.243,29.765 1,30 5.775,30.375 14.472,30.525 19.928,30.525 6.375,30.7 5.775,31.025 14.973,31.177 19.427,31.177 15.625,31.678 18.775,31.678 16.385,31.993 18.015,31.993 1,32 6.34,32.72 33.45,33.25 35.3,33.35 1,34 66,34 14.15,34.075 14.81,34.075 37.29,34.625 37.95,34.625 14.81,34.725 37.29,35.275 37.95,35.275 14.15,35.375 14.81,35.375 37.29,35.925 37.95,35.925 1,36 66,36 16.775,36.625 18.65,36.75 34.9,37.9 1,38 34.085,38.007 35.715,38.007 66,38 33.325,38.322 36.475,38.322 32.673,38.823 37.127,38.823 32.172,39.475 37.628,39.475 1,40 66,40 31.857,40.235 37.943,40.235 55.87,40.34 60.95,40.34 31.75,41.05 38.05,41.05 31.857,41.865 37.943,41.865 66,42 9.75,42.378 11.75,42.378 32.172,42.625 37.628,42.625 9.128,43 12.372,43 32.673,43.277 37.127,43.277 16.85,43.6 33.325,43.778 36.475,43.778 66,44 34.085,44.093 35.715,44.093 28.6,44.2 27.785,44.307 29.415,44.307 27.025,44.622 30.175,44.622 20.175,44.725 9.128,45 12.372,45 26.373,45.123 30.827,45.123 9.75,45.622 11.75,45.622 25.872,45.775 31.328,45.775 66,46 25.557,46.535 31.643,46.535 25.45,47.35 31.75,47.35 6.34,47.96 11.42,47.96 13.96,47.96 59.68,47.96 1,48 25.557,48.165 31.643,48.165 25.872,48.925 31.328,48.925 26.373,49.577 1,50 27.025,50.078 30.175,50.078 27.785,50.393 29.415,50.393 43.17,50.5 39.275,51.175 44.05,51.4 66,52 59.68,53.04 10.75,54 66,54 42.45,55.025 20.31,55.58 58.41,55.58 60.95,55.58 66,56 29.825,57.025 32.8,57.025 66,58 13.96,58.12 16.5,58.12 24.12,58.12 57.14,58.12 59.68,58.12 10.15,60.66 25.39,60.66 58.41,60.66 43.1,62.875 44.44,63.2 49.52,63.2 9,69 11,69 13,69 15,69 21,69 23,69 25,69 27,69 29,69 31,69 36,69 38,69 40,69 42,69 44,69 50,69 52,69 54,69 56,69 58,69
  other v3: 17.375,7.325 19.225,7.325 17.575,8.175 19.025,8.175 23.2,13.825 41.13,19.5 41.13,20.525 35.5,34.5 36.7,34.5 35.875,34.525 36.325,34.525 15.4,34.7 15.775,34.7 16.225,34.7 16.6,34.7 35.275,34.9 35.65,34.9 36.1,34.9 36.55,34.9 15.55,35.1 16,35.1 16.45,35.1 16.825,35.1 35.5,35.3 35.875,35.3 36.325,35.3 36.7,35.3 15.775,35.475 16.225,35.475 15.4,35.5 16.6,35.5 51,49.875 40.775,50.845 35.275,51.9 49.3,54.375 46.6,54.4 47.2,59.625 30.725,60.25
LED_Axis_gn: R212.1 TP261.1 X400a.21 X400b.21 | length 59
  Mid Layer 6 w0.15: v3(18.503,43.073) 19.65,44.22 19.65,44.943 20.399,45.692 20.399,48.576 20.172,48.803 20.172,53.098 v3(19.77,53.5) ; v3(31.775,52.275) 31.775,49.857 38.931,42.701 38.931,34.231 33.9,29.201 v3(33.9,29.05)
  Bottom Side w0.15: X400a.21@16,42.3 17.491,42.3 18.251,43.059 18.489,43.059 v3(18.503,43.073) ; v3(19.77,53.5) 19.805,53.465 19.805,53.053 19.927,52.93 21.876,52.93 22.29,52.516 28.575,52.516 ; TP261.1@28.55,53.4 28.55,52.541 28.575,52.516 ; v3(31.775,52.275) 31.534,52.516 28.575,52.516 ; v3(33.9,29.05) 34.199,29.05 35.549,27.7 X400b.21@36.1,27.7
LED_Axis_rd: R211.1 TP258.1 X400a.19 X400b.19 | length 55.6
  Mid Layer 6 w0.15: v3(18.075,43.5) 18.079,43.504 18.495,43.504 19.347,44.357 19.347,45.068 20.093,45.814 20.093,48.45 19.868,48.675 19.868,51.948 19.77,52.046 v3(19.77,52.1) ; v3(31.3,52.1) 31.3,49.9 38.625,42.575 38.625,34.35 33.5,29.225 v3(33.5,28.65)
  Bottom Side w0.15: X400a.19@16,42.7 17.431,42.7 18.037,43.306 18.037,43.462 v3(18.075,43.5) ; TP258.1@21.45,52.1 v3(31.3,52.1) ; v3(33.5,28.65) 34.175,28.65 35.525,27.3 X400b.19@36.1,27.3
  Bottom Side w0.2: v3(19.77,52.1) TP258.1@21.45,52.1
MotorTemp: Q400.2 R427.1 TP432.1 X400a.42 X400b.42 | length 62.6
  Mid Layer 6 w0.15: v3(25.625,31.7) 25.625,36.7 23.625,38.7 v3(23.6,38.7) 23.6,53.7 27.251,57.351 v3@27.251,63.526 ; v3@27.251,63.55 v3@27.251,63.526 ; v3(27.275,63.55) v3@27.251,63.526
  Bottom Side w0.15: X400a.42@19.4,38.3 23.2,38.3 v3(23.6,38.7) ; v3(25.625,31.7) X400b.42@32.7,31.7 ; v3(27.275,63.55) 29.275,63.55 29.7,63.125 39.49,63.125 40.499,64.134 40.499,64.65 ; R427.1@41.13,64.65 41.125,64.645 41.125,64.225 41.275,64.075 Q400.2@41.275,63.775
  Bottom Side w0.2: TP432.1@39.5,64.65 40.499,64.65 R427.1@41.13,64.65
NetC208_2: C208.2 U203.2 | length 1.6
  Bottom Side w0.2: U203.2@17.175,55.575 17.175,54.55 17.225,54.5 17.225,54.075 C208.2@17.3,54
NetC209_1: C209.1 U203.6 | length 1.6
  Bottom Side w0.2: C209.1@14.45,54 14.516,54.066 14.516,54.491 14.565,54.54 14.565,55.565 U203.6@14.575,55.575
NetC210_1: C210.1 U203.1 | length 1.1
  Bottom Side w0.2: U203.1@17.825,55.575 17.825,55.608 17.92,55.703 18.203,55.703 18.3,55.8 C210.1@18.8,55.8
NetC210_2: C210.2 U203.3 | length 3.4
  Bottom Side w0.2: U203.3@16.606,55.656 U203.3@16.525,55.575 16.525,56.55 16.691,56.716 18.785,56.716 C210.2@18.8,56.7
NetC211_1: C211.1 U203.4 | length 1.8
  Bottom Side w0.2: U203.4@15.875,55.575 15.875,54.467 16.325,54.017 C211.1@16.325,54
NetC211_2: C211.2 U203.5 | length 1.7
  Bottom Side w0.2: U203.5@15.225,55.575 15.225,54.6 15.425,54.4 C211.2@15.425,54
NetC402_1: C402.1 R406.2 TP434.1 | length 5.4
  Top Side w0.15: C402.1@52.7,40.2 54.75,40.2 v2(55.3,39.65)
  Top Side w0.2: C402.1@52.7,40.2 52.7,39.725 52.725,39.7 R406.2@52.725,38.91
  Bottom Side w0.2: TP434.1@54.1,39.575 55.225,39.575 v2(55.3,39.65)
NetC403_1: C403.1 R407.2 TP435.1 | length 6.3
  Top Side w0.15: C403.1@52.7,30.4 54.202,30.4 55.125,31.323 v2(55.125,31.775)
  Top Side w0.2: C403.1@52.7,30.4 52.7,29.9 52.725,29.875 R407.2@52.725,29.135
  Bottom Side w0.2: TP435.1@53.4,31.825 53.45,31.775 v2(55.125,31.775)
NetC404_1: C404.1 R408.2 TP436.1 | length 3.3
  Top Side w0.15: v2@53.6,19.3 v2(53.625,19.275)
  Top Side w0.2: C404.1@52.7,20.6 52.7,20.1 52.725,20.075 R408.2@52.725,19.31 ; R408.2@52.715,19.3 v2@53.6,19.3
  Bottom Side w0.2: v2(53.625,19.275) TP436.1@53.625,20.4
NetC415_2: C415.2 C416.2 R429.1 U400.6
  other v3: 41.8,52.45 40.775,52.575 42.225,52.83 36.3,52.9 36.8,52.9 37.3,52.9 37.8,52.9 38.3,52.9 39.325,52.9 41.7,53.05
NetC417_2: C417.2 U400.7 | length 1.4
  Bottom Side w0.2: U400.7@38.05,52.425 38.05,52.41 38,52.36 38,51.825 38.175,51.65 C417.2@38.175,51.15
NetC418_1: C418.1 D401.2 RN400.3 TP439.1 U401.1 | length 5.5
  Bottom Side w0.2: RN400.3@49.95,12.845 49.95,13.275 50.35,13.675 U401.1@50.35,14.225 51.575,14.225 C418.1@51.6,14.25 ; D401.2@51.6,15.275 C418.1@51.6,14.25 ; TP439.1@53.225,14.25 C418.1@51.6,14.25
NetC419_1: C419.1 D402.2 RN400.2 TP440.1 U401.3 | length 6.8
  Bottom Side w0.2: TP440.1@47.5,17.45 47.5,17.283 47.05,16.833 47.05,15.475 47.249,15.276 D402.2@47.8,15.275 ; D402.2@47.8,15.275 C419.1@47.8,14.25 49.025,14.25 U401.3@49.05,14.225 49.05,13.675 49.441,13.284 49.441,12.854 RN400.2@49.45,12.845
NetC505_1: C505.1 R503.2 RN502.5 RN502.6 TP423.1 U501.1 | length 7.3
  Mid Layer 6 w0.15: v3(42.945,57.12) 42.978,57.12 43.133,57.275 44.495,57.275 v3(44.92,56.85)
  Bottom Side w0.15: TP423.1@41.975,58.775 42.927,57.823 42.927,57.473
  Bottom Side w0.2: 42.927,57.473 42.927,57.138 v3(42.945,57.12) RN502.6@42.945,56.6 ; C505.1@44.9,57.85 44.9,56.87 v3(44.92,56.85) 44.968,56.802 45.398,56.802 45.597,56.603 45.88,56.603 45.975,56.508 U501.1@45.975,56.225
NetC507_1: C507.1 R505.2 RN503.3 RN503.4 TP425.1 U501.7 | length 9
  Mid Layer 6 w0.15: v3(51.68,56.85) 52.105,57.275 53.24,57.275 v3(53.655,56.86)
  Bottom Side w0.2: U501.7@49.875,56.225 49.875,57.275 50.45,57.85 C507.1@51.7,57.85 51.68,57.83 v3(51.68,56.85) ; RN503.3@53.655,56.6 v3(53.655,56.86) RN503.4@53.655,57.12 53.655,57.555 54.2,58.1 TP425.1@54.2,58.9
NetD204_1: D204.1 R202.2 | length 1
  Bottom Side w0.2: D204.1@44.575,3.325 45.285,3.325 45.29,3.33 R202.2@45.6,3.33
NetD205_1: D205.1 R203.2 | length 1
  Bottom Side w0.2: R203.2@41.8,3.33 42.11,3.33 42.115,3.325 D205.1@42.825,3.325
NetDS200_2: DS200.2 R211.2 | length 2.2
  Top Side w0.2: v2(17.6,52.1) DS200.2@18.555,52.1
  Bottom Side w0.2: v2(17.6,52.1) R211.2@18.83,52.1
NetDS201_2: DS201.2 R212.2 | length 1.8
  Top Side w0.2: v2(18.55,54.35) 18.555,54.345 DS201.2@18.555,53.5
  Bottom Side w0.2: v2(18.55,54.35) 18.55,54.308 18.825,54.033 18.825,53.505 R212.2@18.83,53.5
NetQ200_2: Q200.2 R205.2 | length 1.8
  Bottom Side w0.15: R205.2@43.045,12.575 43.065,12.555 Q200.2@43.065,10.82
NetQ200_4: Q200.4 R204.2 | length 1.8
  Bottom Side w0.15: Q200.4@45.605,10.82 45.605,12.56 R204.2@45.62,12.575
NetR200_1: R200.1 U200.4 | length 1.2
  Bottom Side w0.2: U200.4@60.085,43.05 R200.1@60.085,44.255
NetR204_1: R204.1 U201.4 | length 2.4
  Bottom Side w0.15: R204.1@44.68,12.575 44.68,13.08 44.825,13.225 45.55,13.225 45.7,13.375 U201.4@45.7,14.155
NetR205_1: R205.1 U202.4 | length 2.3
  Bottom Side w0.15: R205.1@42.105,12.575 42.105,13.08 42.25,13.225 42.825,13.225 43,13.4 U202.4@43,14.155
NetR209_1: R209.1 SW1.10 TP255.1 | length 3.9
  Top Side w0.2: v2@32.675,7.68 SW1.10@32.675,8.907 R209.1@32.675,10.15
  Bottom Side w0.2: v2(32.68,7.675) 33.025,7.33 TP255.1@33.025,6.375
NetR210_2: R210.2 SW1.8 TP256.1 | length 3.4
  Top Side w0.2: SW1.8@33.945,2.893 34.843,2.893 v2(34.85,2.9)
  Bottom Side w0.2: R210.2@34.85,4.13 v2(34.85,2.9) 36,2.9 TP256.1@36.1,3
NetR422_2: R422.2 U400.1 | length 2.1
  Bottom Side w0.2: R422.2@35.275,54.845 35.295,54.825 36.325,54.825 36.6,54.55 U400.1@36.6,53.925
NetR423_1: R423.1 R424.2 TP437.1 U400.2 | length 4.1
  Bottom Side w0.2: U400.2@37.075,54.075 R423.1@37.075,55.18 R424.2@38.1,55.18 39.258,55.18 39.678,55.6 TP437.1@39.875,55.6
NetR425_2: R425.2 TP438.1 U400.9 | length 3.7
  Bottom Side w0.2: TP438.1@35.125,49.725 35.875,50.475 35.875,50.825 36.22,51.17 R425.2@36.75,51.17 36.75,51.55 37.075,51.875 U400.9@37.075,52.275
NetRN504_5: RN504.5 RN504.6 TP427.1 U501.9 | length 5.8
  Mid Layer 6 w0.15: v3(51.605,51.53) 51.825,51.31 v3(51.825,47.825)
  Bottom Side w0.15: U501.9@50.525,50.975 50.525,51.189 50.643,51.307 50.857,51.307 51.08,51.53 v3(51.605,51.53) RN504.6@51.605,52.05
S2_A_HsDgin1: R507.1 TP416.1 U501.3 X400a.14 X400b.14 | length 61.2
  Mid Layer 6 w0.15: v3(30.675,43.9) 30.7,43.875 30.7,41.95 30.075,41.325 30.075,34.125 31.325,32.875 v3(31.325,26.1) ; v3(45.375,48.5) 47.275,50.4 v3(47.275,56.225)
  Bottom Side w0.15: X400a.14@19.4,43.9 27.454,43.9 27.682,43.672 29.045,43.672 29.148,43.775 29.625,43.775 29.75,43.9 v3(30.675,43.9) 30.852,43.9 31.014,44.061 33.527,46.575 43.651,46.575 45.343,48.267 45.343,48.468 v3(45.375,48.5) ; v3(31.325,26.1) X400b.14@32.7,26.1 ; v3(47.275,56.225) 47.275,57.25 47.42,57.395 R507.1@47.42,57.85
  Bottom Side w0.2: TP416.1@45.5,59.425 46.375,59.425 47.42,58.38 R507.1@47.42,57.85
